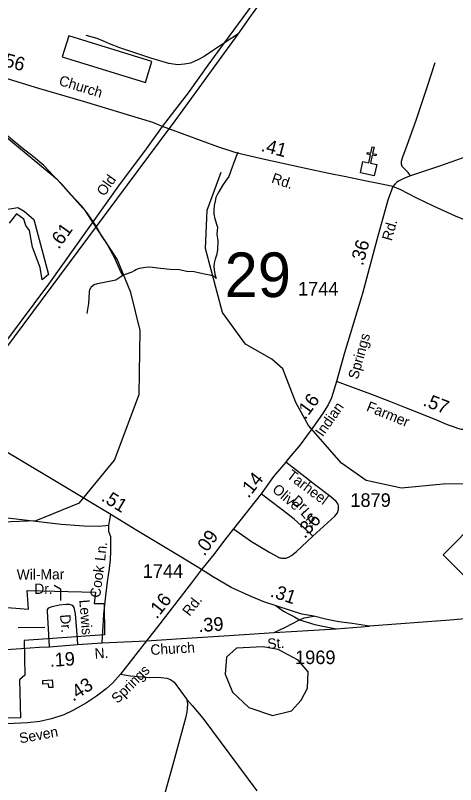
# Model space of a CAD drawing. Extents: x 2206922 to 2357709, y 510027 to 673830.
# Drawn here: x 2282697 to 2286750, y 528698 to 535777 of the extents above; entities that cross this region are included whole.
import ezdxf

# ---------------------------------------------------------------- set-up
doc = ezdxf.new("R2010")
doc.units = 0
for name, color, linetype in [('Exist Boundary Political City Limit New', 7, 'Continuous'), ('Exist Cultural Church CELL', 7, 'Continuous'), ('Exist Cultural Warehouse Building Footprint', 7, 'Continuous'), ('Exist Hydrographic Creek Single Shore', 7, 'Continuous'), ('Exist Hydrographic Misc Water Feature', 7, 'Continuous'), ('Exist Hydrographic Pond Under 1500 Sq Ft', 7, 'Continuous'), ('Exist Railroad Mainline', 7, 'Continuous'), ('Exist Road Non-System Type 51', 7, 'Continuous'), ('Exist Road Non-System Type 51 Label', 7, 'Continuous'), ('Exist Road Primary NC Attributed', 7, 'Continuous'), ('Exist Road Primary NC Service Mileage Hundredths English Label', 7, 'Continuous'), ('Exist Road Primary NC Shield CELL', 7, 'Continuous'), ('Exist Road Secondary Mileage Hundredths English Label', 7, 'Continuous'), ('Exist Road Secondary Structure Standard Bridge Number Label', 7, 'Continuous'), ('Exist Road Secondary Type 51 Attributed', 7, 'Continuous'), ('Exist Road Secondary Type 51 Label', 7, 'Continuous'), ('Exist Road Secondary Type 51 Number Label', 7, 'Continuous'), ('Map Preparation Boundary City Limit Buffer Line', 7, 'Continuous')]:
    doc.layers.add(name, color=color, linetype=linetype)

msp = doc.modelspace()

# ---------------------------------------------------------------- linework, layer by layer
at = {"layer": 'Exist Boundary Political City Limit New'}
for points in [[(2282568.5, 533984.8), (2282718.5, 534009.8), (2282777, 533976.4), (2282868.5, 533897.2), (2283003.5, 533390.9), (2282943.8, 533342.3), (2282924, 533455.9), (2282856.2, 533642.7), (2282827, 533797.1), (2282793.5, 533842.9), (2282774.5, 533902), (2282706, 533951.4), (2282639.2, 533863.8)], [(2282230.8, 530359.2), (2282818.5, 530313.3), (2282806, 530484.4), (2283435.8, 530467.7), (2283423.2, 530363.4), (2283515, 530363.4), (2283518.8, 530076.2), (2282777, 530025.4), (2282785.2, 529704.2), (2282735.2, 529662.4), (2282742.8, 529311.6), (2281931, 529291.8)]]:
    msp.add_lwpolyline(points, dxfattribs=at)
at = {"layer": 'Exist Cultural Church CELL'}
msp.add_lwpolyline([(2285895.3, 534430.8), (2285951.1, 534419), (2285966.9, 534493.5), (2285935.6, 534500.2), (2285939, 534515.8), (2285970.3, 534509.1), (2285982.8, 534567.9), (2285998.5, 534564.6), (2285986, 534505.8), (2286017.2, 534499.1), (2286013.9, 534483.5), (2285982.6, 534490.2), (2285966.7, 534415.7), (2286023.1, 534403.6), (2286000.9, 534299.4), (2285873.1, 534326.7)], close=True, dxfattribs=at)
at = {"layer": 'Exist Cultural Warehouse Building Footprint'}
for p, q in [((2283189.1, 535589.8), (2283129.2, 535396.4)), ((2283953.6, 535352.6), (2283189.1, 535589.8)), ((2283129.2, 535396.4), (2283893.7, 535159.3)), ((2283893.7, 535159.3), (2283953.6, 535352.6))]:
    msp.add_line(p, q, dxfattribs=at)
at = {"layer": 'Exist Hydrographic Creek Single Shore'}
msp.add_lwpolyline([(2289423.1, 528967.3), (2289128, 529261.8), (2288810, 529468.2), (2288650.1, 529625.6), (2288430.1, 530013.7), (2288123.1, 530820.1), (2287870.1, 531117), (2287853, 531176.5), (2287718.1, 531307.1), (2287202, 531310.9), (2286834.1, 531465.9), (2286634, 531463.3), (2286251, 531425.1), (2285926, 531497.3), (2285699, 531656), (2285396.9, 532003.1), (2285278, 532215.5), (2285158, 532522.8), (2285058, 532613.4), (2284815, 532752.8), (2284604, 533042.3), (2284447.9, 533632.5), (2284461.9, 533983.1), (2284591.9, 534334.7)], dxfattribs=at)
at = {"layer": 'Exist Hydrographic Misc Water Feature'}
for points in [[(2281654.9, 531268.5), (2281831.1, 531202.5), (2282348, 531106.9), (2282888.9, 531128.8), (2283288, 531291.3), (2283609.1, 531684.9), (2283836.1, 532287.1), (2283846.9, 532877.2), (2283761, 533226.5), (2283633.1, 533534.1), (2283346, 533972.8), (2283085, 534263.4), (2282563.9, 534696.9), (2282220.9, 534903.9)], [(2283687, 533384.7), (2283664.6, 533424.5), (2283613.8, 533541.9), (2283536.5, 533683.2), (2283487.7, 533754.7), (2283440.9, 533836.2), (2283364, 533949.4), (2283305.2, 534022.8), (2283206.6, 534127.8), (2283123.5, 534223), (2283044.8, 534304.2), (2282958, 534395.3), (2282863.3, 534474.4), (2282756.7, 534557.3), (2282559.2, 534719.4), (2282430.2, 534834.1), (2282329.5, 534907.1)], [(2284745.9, 534518), (2284714.7, 534437.8), (2284679.4, 534345.5), (2284662, 534295.3), (2284638.2, 534259.2), (2284604.8, 534210.9), (2284569.5, 534154.5), (2284557.4, 534130.5), (2284543.9, 534100.3), (2284536.3, 534068.3), (2284528.5, 534028.2), (2284523, 533984.2), (2284523.2, 533946.2), (2284531.8, 533904.4), (2284558.5, 533826.6), (2284552.9, 533764.6), (2284559.7, 533700.7), (2284558.5, 533622.8), (2284550.7, 533578.7), (2284535.3, 533534.6), (2284527.5, 533496.5), (2284523.8, 533468.5), (2284528.3, 533434.6), (2284532.4, 533394.7), (2284547, 533356.8)], [(2283687, 533384.7), (2283772.7, 533417.5), (2283792.8, 533429.7), (2283804.5, 533437.8), (2283840.6, 533450.1), (2283896.1, 533460.7), (2283936.1, 533463), (2284032.3, 533451.9), (2284122.3, 533442.8), (2284206.2, 533437.6), (2284276.5, 533422.2), (2284342.5, 533420.8), (2284396.5, 533407.4), (2284454.5, 533395.9), (2284486.7, 533388.2), (2284522.8, 533376.6), (2284547, 533356.8)], [(2283358.5, 533033.9), (2283373.7, 533125.9), (2283378.8, 533229.9), (2283382.5, 533257.9), (2283384.5, 533262), (2283390.5, 533264), (2283396.2, 533278), (2283423.9, 533300.3), (2283454.1, 533308.6), (2283543.7, 533327.4), (2283621.6, 533342.1), (2283687, 533384.7)], [(2283034.5, 529662.7), (2283041.1, 529592.7), (2283005.2, 529590.4), (2283000.7, 529626.4), (2282950.7, 529621.9), (2282948.4, 529655.8), (2283034.5, 529662.7)]]:
    msp.add_lwpolyline(points, dxfattribs=at)
at = {"layer": 'Exist Hydrographic Pond Under 1500 Sq Ft'}
msp.add_lwpolyline([(2285063.1, 529333.8), (2285238, 529376.1), (2285328, 529476), (2285386.1, 529586.3), (2285393, 529737.1), (2285299.9, 529843.9), (2285116, 529942.7), (2284974.1, 529965.2), (2284733, 529953.7), (2284641.9, 529870.2), (2284627, 529713.1), (2284695, 529547.8), (2284845.9, 529407), (2285063.1, 529333.8)], dxfattribs=at)
at = {"layer": 'Exist Railroad Mainline'}
for points in [[(2285970.5, 537863.7), (2285956.5, 537803.4), (2285921.6, 537687.1), (2285890.8, 537566.8), (2285824.4, 537406.4), (2285759.6, 537259.8), (2285665.8, 537047.2), (2285565.6, 536858.3), (2285457.6, 536655.3), (2285313.9, 536412.1), (2285112.9, 536116.5), (2284868.2, 535778.3), (2284743.9, 535605.3), (2284140, 534774), (2284110.5, 534734.3)], [(2284110.5, 534734.3), (2283441.2, 533834.1), (2282177.9, 532137), (2282115.6, 532054.8)]]:
    msp.add_lwpolyline(points, dxfattribs=at)
at = {"layer": 'Exist Road Non-System Type 51'}
for p, q in [((2284743.9, 535605.3), (2284621.1, 535523.8)), ((2283559, 531086.6), (2283576.2, 531184.1)), ((2283012.2, 529967.4), (2283008.8, 530023.5)), ((2283265.4, 530038.4), (2283269.4, 529988.5))]:
    msp.add_line(p, q, dxfattribs=at)
for points in [[(2284621.1, 535523.8), (2284511.5, 535451), (2284433.9, 535398.4), (2284378.3, 535368), (2284310.5, 535337.3), (2284254.7, 535326.9), (2284192.8, 535322.1), (2284108.7, 535335.4), (2283944.4, 535383.9), (2283659.6, 535479.2), (2283563.3, 535514.1), (2283509, 535539.6), (2283450.9, 535563.2), (2283348.8, 535592.2)], [(2286333.2, 534300.4), (2286311.6, 534330.9), (2286276, 534366.5), (2286258.2, 534386.8), (2286250.6, 534407.2), (2286251.9, 534435.2), (2286264.6, 534474.6), (2286304, 534581.4), (2286386.5, 534811.2), (2286492.1, 535124.5), (2286562, 535344.5)], [(2285435.6, 530985.1), (2285373.1, 531043.3), (2285329.1, 531081.7), (2285265.1, 531140), (2285165.7, 531216.7), (2285026.5, 531321.8), (2284958.4, 531373)], [(2281947.5, 530832.8), (2281950.1, 530833.7), (2281952, 530855.6), (2281981.3, 530929.8), (2282018.9, 530972.3), (2282112.3, 531023.2), (2282353.1, 531155.2), (2282400.9, 531167.7), (2282472.9, 531168.4), (2282650.8, 531150.1), (2283119.2, 531096.4), (2283331.2, 531080.6), (2283465.1, 531077.7), (2283559, 531086.6)], [(2283497.2, 530002.7), (2283500.6, 530062.6), (2283506.4, 530154.8), (2283512.7, 530266.7), (2283529.2, 530436.7), (2283549.6, 530588.8), (2283561.1, 530660.9), (2283572, 530766.9), (2283577.2, 530848.9), (2283576.6, 530916.9), (2283576.1, 530978.9), (2283557.5, 531028.6), (2283559, 531086.6)], [(2283008.8, 530023.5), (2282992.8, 530289.7), (2282992.6, 530309.7), (2283004.5, 530323.9), (2283034.3, 530336.1), (2283100, 530352.7), (2283163.9, 530359.2), (2283192.1, 530357.7), (2283220.1, 530349.9), (2283234.3, 530328), (2283246.9, 530270.2), (2283265.4, 530038.4)], [(2285097.6, 530344), (2285165.1, 530295.8), (2285224.2, 530263.2), (2285266, 530241.2), (2285311.8, 530214.8)], [(2285079.4, 530099.4), (2285189.2, 530148.7), (2285241.1, 530177.6), (2285311.8, 530214.8)], [(2285311.8, 530214.8), (2285356.7, 530231.9), (2285445.9, 530248.7)], [(2285311.8, 530214.8), (2285382.4, 530194.2), (2285452.6, 530173), (2285556.7, 530149.9), (2285648.8, 530130.9)], [(2283666.4, 529713.9), (2283756.7, 529698.6), (2283901.6, 529688.4), (2284038.9, 529684.6), (2284091, 529678.3), (2284126.6, 529665.6), (2284158.4, 529641.4), (2284276.6, 529481.1)], [(2284276.6, 529481.1), (2284280.4, 529439.2), (2284277.9, 529398.5), (2284275.3, 529367.9), (2284262.6, 529310.7), (2284143.1, 528870.6), (2284046.5, 528522.2)], [(2284276.6, 529481.1), (2284323.6, 529426.4), (2284422.8, 529308.2), (2284582.9, 529094.5), (2284919.3, 528640.8)]]:
    msp.add_lwpolyline(points, dxfattribs=at)
at = {"layer": 'Exist Road Non-System Type 51 Label'}
for points in [[(2283054.1, 530533.2), (2283113.5, 530500.5), (2283113.5, 530393.5)], [(2282721.6, 530144), (2282968, 530146.9)]]:
    msp.add_lwpolyline(points, dxfattribs=at)
at = {"layer": 'Exist Road Primary NC Attributed'}
for points in [[(2284411.6, 530678.1), (2284214.2, 530797.5), (2283952.8, 530955.2), (2283801.2, 531046.8), (2283576.2, 531184.1), (2283152.9, 531439.8), (2282686.4, 531718.3), (2282321.6, 531930.7), (2282085.1, 532073.2)], [(2285958.4, 530155.7), (2285798.4, 530182.3), (2285674.9, 530195.7), (2285552, 530219.8), (2285445.9, 530248.7), (2285333.8, 530268.1), (2285229, 530299.4), (2285097.6, 530344), (2284985.6, 530380.2), (2284845.8, 530437.5), (2284683.1, 530513.4), (2284511, 530614.2), (2284411.6, 530678.1)], [(2292618.9, 530634.6), (2292485.4, 530642.3), (2292306.2, 530652.7), (2292156.1, 530658.1), (2291964.5, 530661.8), (2291801.8, 530656.3), (2291552.4, 530641.9), (2291440.3, 530638.2), (2291308.3, 530627.4), (2291147.4, 530611.1), (2290659.4, 530571.3), (2290092.9, 530522.3), (2289425.7, 530470.1), (2289054.2, 530433.1), (2288880.6, 530415.8), (2288356.3, 530365.1), (2287334, 530268.1), (2286695.5, 530212.6), (2285958.4, 530155.7)]]:
    msp.add_lwpolyline(points, dxfattribs=at)
at = {"layer": 'Exist Road Primary NC Shield CELL'}
msp.add_lwpolyline([(2286633.8, 530812.9), (2286966.8, 531145.9), (2287299.8, 530812.9), (2286966.8, 530479.9)], close=True, dxfattribs=at)
at = {"layer": 'Exist Road Secondary Type 51 Attributed'}
msp.add_line((2284110.5, 534734.3), (2284052.9, 534755.5), dxfattribs=at)
for points in [[(2284052.9, 534755.5), (2284113.4, 534833.7), (2284291.2, 535065.2), (2284470.7, 535318.9), (2284621.1, 535523.8), (2284923.6, 535935.8), (2285099, 536183.8), (2285240.1, 536396.2), (2285435.9, 536733.2), (2285556.6, 536981.3), (2285659.6, 537210.2), (2285761.3, 537473.5), (2285841.4, 537697.3), (2285885.9, 537843.6)], [(2289311.3, 535899.1), (2289117.1, 535763.4), (2289054.2, 535721.1), (2288907.5, 535622.3), (2288636.5, 535439.9), (2288317.6, 535209.1), (2288003.7, 535010.1), (2287856.7, 534924.9), (2287743.2, 534867.8), (2287571.9, 534792.3), (2287338.7, 534693.4), (2287154.4, 534608.1), (2286986.7, 534531), (2286811.6, 534463.3), (2286600.2, 534390.7), (2286333.2, 534300.4), (2286278.6, 534277.5), (2286225, 534252.3), (2286209.7, 534242.1), (2286194.7, 534227.9), (2286171.8, 534201.2)], [(2284052.9, 534755.5), (2283961.3, 534789.9), (2283323.2, 534983.2), (2282912.6, 535104), (2282643.2, 535186.7), (2282480.4, 535236.3), (2282310.1, 535285.9), (2282184.3, 535321.5), (2281964.4, 535368.5), (2281579.2, 535436), (2281350.4, 535471.6), (2281196.6, 535499.5)], [(2282085.1, 532073.2), (2283004.5, 533304.3), (2283663.4, 534229.8), (2283890.3, 534527.7), (2284052.9, 534755.5)], [(2286171.8, 534201.2), (2286099.3, 534216.4), (2285915, 534253.3), (2285738.3, 534291.5), (2285583.2, 534323.2), (2285383.7, 534365.2), (2284989.6, 534449.2), (2284737.9, 534510.2), (2284561.2, 534568.7), (2284110.5, 534734.3)], [(2286171.8, 534201.2), (2286127.3, 534077.8), (2286024.3, 533712.8), (2285891.6, 533217.4), (2285726.9, 532672.1), (2285653.4, 532407.5)], [(2287497.8, 533478.3), (2287359, 533595.7), (2287206.5, 533726.7), (2287168.4, 533749.6), (2287092.1, 533790.3), (2286926.8, 533856.5), (2286747.6, 533930.2), (2286546.8, 534021.8), (2286393, 534095.6), (2286305.2, 534141.4), (2286246.8, 534171.9), (2286171.8, 534201.2)], [(2287497.8, 533478.3), (2287480.8, 533432.1), (2287391.1, 533189.4), (2287245.1, 532786.3), (2287088.8, 532331.5), (2287009.2, 532130.4), (2286956.7, 532009.6), (2286941.5, 531992.6), (2286922.6, 531979.8), (2286905.6, 531973.6), (2286884.7, 531968), (2286843.8, 531964.9), (2286803.3, 531967), (2286771.3, 531975.5), (2286730.4, 531989.7), (2286676.4, 532009.6), (2286581.7, 532048.5), (2286453.9, 532101.3), (2286283.5, 532167.4), (2286145, 532222.8), (2285968.2, 532291), (2285793.5, 532357.1), (2285653.4, 532407.5)], [(2285653.4, 532407.5), (2285607.4, 532256.9), (2285576.2, 532194.4), (2285525.1, 532110.5), (2285435.6, 531985.5), (2285317.7, 531824.9), (2285200.4, 531683.7), (2285185.6, 531666)], [(2285185.6, 531666), (2285074.1, 531532.7), (2284958.4, 531373), (2284705.6, 531051.9)], [(2285435.6, 530985.1), (2285570.5, 531107.3), (2285637.3, 531167), (2285661.4, 531199.6), (2285672.6, 531230.4), (2285672.8, 531243.7), (2285672.8, 531259.3), (2285668.5, 531279.2), (2285651.5, 531303.4), (2285600.3, 531346), (2285464, 531451.2), (2285309.2, 531570.5), (2285185.6, 531666)], [(2284705.6, 531051.9), (2284623.2, 530948.1), (2284523.8, 530814.5), (2284411.6, 530678.1)], [(2284705.6, 531051.9), (2284870.3, 530935.3), (2285040.7, 530833), (2285111.8, 530794.6), (2285122.3, 530789.4), (2285131.7, 530786.3), (2285142.3, 530783.8), (2285151.5, 530783.3), (2285164.4, 530781.3), (2285177.2, 530782.2), (2285187.4, 530783.1), (2285197, 530786.1), (2285218.9, 530794.1), (2285238.2, 530806), (2285286.5, 530843), (2285383.5, 530933.9), (2285435.6, 530985.1)], [(2284411.6, 530678.1), (2284327.8, 530565.9), (2284028.1, 530177.9), (2283902.9, 530022.5)], [(2283902.9, 530022.5), (2284226.6, 530041.6), (2284664, 530071.6), (2285079.4, 530099.4), (2285648.8, 530130.9), (2285958.4, 530155.7)], [(2283902.9, 530022.5), (2283666.4, 529713.9), (2283595, 529633.7), (2283534.1, 529579.4), (2283444.3, 529512.9), (2283352.3, 529451.9), (2283224.9, 529378.8), (2283141.8, 529340), (2283031, 529303.4), (2282922.5, 529277.9), (2282808.3, 529266.8), (2282623.3, 529257.9), (2282479.3, 529254.6), (2282338.8, 529256.1), (2282113.6, 529239.1), (2281936.7, 529245.9), (2281929.2, 529245.6), (2281771.3, 529238.9), (2281379.5, 529241.2), (2280919.7, 529234.9)], [(2282295.5, 529925.2), (2282366.3, 529930.8), (2282613.3, 529941.9), (2282751.6, 529951.1), (2282914.7, 529961.9), (2283012.2, 529967.4), (2283269.4, 529988.5), (2283497.2, 530002.7), (2283902.9, 530022.5)]]:
    msp.add_lwpolyline(points, dxfattribs=at)
at = {"layer": 'Map Preparation Boundary City Limit Buffer Line'}
for points in [[(2282568.5, 533984.8), (2282718.5, 534009.8), (2282777, 533976.4), (2282868.5, 533897.2), (2283003.5, 533390.9), (2282943.8, 533342.3), (2282924, 533455.9), (2282856.2, 533642.7), (2282827, 533797.1), (2282793.5, 533842.9), (2282774.5, 533902), (2282706, 533951.4), (2282639.2, 533863.8)], [(2282230.8, 530359.2), (2282818.5, 530313.3), (2282806, 530484.4), (2283435.8, 530467.7), (2283423.2, 530363.4), (2283515, 530363.4), (2283518.8, 530076.2), (2282777, 530025.4), (2282785.2, 529704.2), (2282735.2, 529662.4), (2282742.8, 529311.6), (2281931, 529291.8)]]:
    msp.add_lwpolyline(points, dxfattribs=at)

# ---------------------------------------------------------------- texts
at = {"layer": 'Exist Road Non-System Type 51 Label'}
for s, rotation, p in [('Olive', 319.72669, (2285054.5, 531401.4)), ('Ln.', 311.69109, (2285317.1, 531192.6)), ('Ln.', 84.12756, (2283523.2, 530751.7)), ('Wil-Mar', 0.4121, (2282710.3, 530584)), ('Cook', 82.361, (2283477, 530413.5)), ('Dr.', 359.65645, (2282871.1, 530453.6)), ('Lewis', 274.56665, (2283285.5, 530396.9)), ('Dr.', 274.56665, (2283108.1, 530261.2))]:
    msp.add_text(s, height=95, rotation=rotation, dxfattribs=at).set_placement(p)
at = {"layer": 'Exist Road Primary NC Service Mileage Hundredths English Label'}
for s, rotation, p in [('.51', 328.8708, (2283479.6, 531315.5)), ('.31', 341.24079, (2285035.8, 530431))]:
    msp.add_text(s, height=125, rotation=rotation, dxfattribs=at).set_placement(p)
at = {"layer": 'Exist Road Secondary Mileage Hundredths English Label'}
for s, rotation, p in [('.56', 344.59671, (2282541.4, 535323.2)), ('.41', 345.10099, (2284951.2, 534530.2)), ('.61', 54.55149, (2283096, 533618.8)), ('.36', 74.12195, (2285896.2, 533467.6)), ('.16', 53.88013, (2285366.9, 532051.1)), ('.57', 338.92824, (2286441.7, 532188.5)), ('.14', 51.55777, (2284843, 531327.5)), ('.36', 47.87001, (2285362.1, 530956.5)), ('.09', 54.52286, (2284437, 530794.8)), ('.16', 52.02622, (2283999.1, 530215.4)), ('.39', 3.82852, (2284384.9, 530101.7)), ('.19', 3.56678, (2283016.6, 529781.6)), ('.43', 32.98369, (2283228.9, 529460.1))]:
    msp.add_text(s, height=125, rotation=rotation, dxfattribs=at).set_placement(p)
at = {"layer": 'Exist Road Secondary Structure Standard Bridge Number Label'}
msp.add_text('29', height=410.1, dxfattribs=at).set_placement((2284623.7, 533184.9))
at = {"layer": 'Exist Road Secondary Type 51 Label'}
for s, rotation, p in [('Church', 342.75388, (2283090.4, 535137.7)), ('Old', 54.55149, (2283515, 534106.2)), ('Rd.', 341.65554, (2285047.8, 534239.5)), ('Rd.', 74.12195, (2286160.8, 533695.9)), ('Springs', 74.47574, (2285849.6, 532421.3)), ('Indian', 54.89313, (2285526.5, 531892.2)), ('Farmer', 337.83872, (2285921.4, 532141.1)), ('Tarheel', 322.99996, (2285187.7, 531527.2)), ('Dr.', 317.93981, (2285232.7, 531300)), ('Rd.', 52.02622, (2284300.8, 530241)), ('St.', 3.92362, (2285019.8, 529946.6)), ('Church', 3.37701, (2283943, 529890.7)), ('N.', 3.56678, (2283429.2, 529857.4)), ('Springs', 44.80416, (2283637.2, 529438.4)), ('Seven', 10.45914, (2282741.9, 529077.1))]:
    msp.add_text(s, height=95, rotation=rotation, dxfattribs=at).set_placement(p)
at = {"layer": 'Exist Road Secondary Type 51 Number Label'}
for s, p in [('1744', (2285299.3, 533198.8)), ('1879', (2285780.9, 531253.7)), ('1744', (2283869.9, 530601)), ('1969', (2285272.3, 529807.2))]:
    msp.add_text(s, height=125, dxfattribs=at).set_placement(p)

doc.saveas('drawing.dxf')
